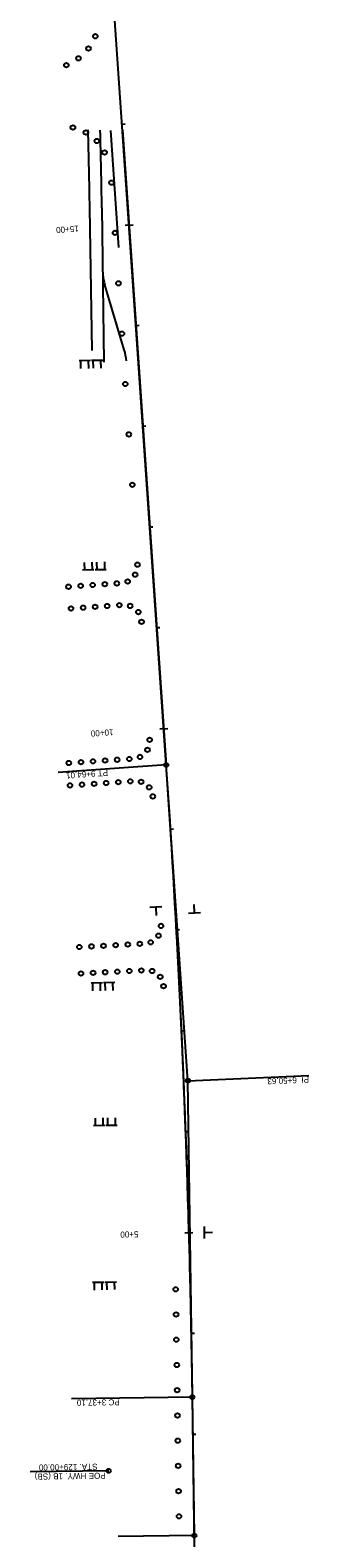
# Model space of a CAD drawing. Extents: x 1665984 to 1683035, y 227404 to 233856.
# Drawn here: x 1677283 to 1677559, y 230111 to 231605 of the extents above; entities that cross this region are included whole.
import ezdxf

# ---------------------------------------------------------------- set-up
doc = ezdxf.new("R2010")
doc.units = 0
for name, color, linetype in [('Default', 7, 'Continuous'), ('Level 47', 7, 'Continuous'), ('R_Horz Alg', 7, 'Continuous'), ('R_Horz Alg Annot', 7, 'Continuous'), ('R_MOT', 7, 'Continuous'), ('R_Striping', 7, 'Continuous'), ('S_EDGE_PAVEMENT', 7, 'Continuous')]:
    doc.layers.add(name, color=color, linetype=linetype)

msp = doc.modelspace()

# ---------------------------------------------------------------- linework, layer by layer
at = {"layer": 'Default'}
for p, q in [((1677413.3, 230736.3), (1677401.4, 230735.7)), ((1677407.4, 230735.8), (1677407.8, 230727.8)), ((1677445.7, 230730.6), (1677445.3, 230738.7)), ((1677439.8, 230730.1), (1677451.7, 230730.8)), ((1677455.1, 230419.7), (1677455.3, 230407.9)), ((1677455.4, 230413.8), (1677463.5, 230414))]:
    msp.add_line(p, q, dxfattribs=at)
at = {"layer": 'Level 47'}
for centre in [(1677347.3, 231598.8), (1677340.5, 231586.7), (1677318.6, 231570.2), (1677330.7, 231576.9), (1677325.1, 231508.4), (1677338, 231503.5), (1677348.8, 231495), (1677356.5, 231483.7), (1677363.4, 231453.8), (1677366.8, 231404), (1677370.2, 231354.1), (1677373.7, 231304.2), (1677377.1, 231254.3), (1677380.6, 231204.4), (1677384, 231154.5), (1677389.2, 231075.3), (1677379.4, 231058.7), (1677386.8, 231065.5), (1677320.8, 231053.5), (1677332.8, 231054.4), (1677344.7, 231055.2), (1677356.7, 231056), (1677368.7, 231056.8), (1677323.2, 231032), (1677335.2, 231032.8), (1677347.1, 231033.6), (1677359.1, 231034.4), (1677371.1, 231035.3), (1677381.9, 231034.5), (1677390, 231028.4), (1677393.2, 231018.7), (1677401.2, 230901.8), (1677333.1, 230879.7), (1677345, 230880.5), (1677357, 230881.3), (1677369, 230882.1), (1677381, 230882.9), (1677391.6, 230884.9), (1677399, 230891.9), (1677321.1, 230878.9), (1677322.2, 230856.7), (1677334.1, 230857.5), (1677346.1, 230858.3), (1677358.1, 230859.1), (1677370.1, 230859.9), (1677382, 230860.7), (1677392.7, 230860.3), (1677400.8, 230854.8), (1677404.3, 230845.8), (1677412.5, 230717.5), (1677402.2, 230701.3), (1677409.9, 230707.8), (1677331.5, 230696.6), (1677343.5, 230697.2), (1677355.5, 230697.8), (1677367.5, 230698.4), (1677379.5, 230699.1), (1677391.4, 230699.7), (1677333.1, 230670.4), (1677345.1, 230671), (1677357.1, 230671.6), (1677369.1, 230672.2), (1677381, 230672.8), (1677393, 230673.4), (1677403.6, 230672.8), (1677411.7, 230667.1), (1677415, 230657.8), (1677427, 230357.5), (1677427.4, 230332.6), (1677427.7, 230307.6), (1677428.1, 230282.6), (1677428.5, 230257.6), (1677428.8, 230232.6), (1677429.2, 230207.6), (1677429.5, 230182.6), (1677429.9, 230157.6), (1677430.3, 230132.6)]:
    msp.add_circle(centre, 2.25, dxfattribs=at)
at = {"layer": 'R_Horz Alg'}
for p, q in [((1677417.6, 230877), (1677316.6, 232344.1)), ((1677445.5, 230113.6), (1677443.6, 230250.7))]:
    msp.add_line(p, q, dxfattribs=at)
msp.add_arc((1665985.6, 230089.6), 11459.2, 0.80558, 3.94011, dxfattribs=at)
at = {"layer": 'R_Horz Alg Annot'}
for p, q in [((1677417.6, 230877), (1677310.4, 230869.6)), ((1677439.2, 230564.2), (1677417.6, 230877)), ((1677443.6, 230250.7), (1677439.2, 230564.2))]:
    msp.add_line(p, q, dxfattribs=at)
for points in [[(1677376.9, 231511.7), (1677373.9, 231511.5)], [(1677376.8, 231411.5), (1677384.8, 231412)], [(1677390.7, 231312.2), (1677387.7, 231312)], [(1677397.5, 231212.4), (1677394.6, 231212.2)], [(1677404.4, 231112.6), (1677401.4, 231112.4)], [(1677411.3, 231012.9), (1677408.3, 231012.7)], [(1677411.2, 230912.6), (1677419.2, 230913.2)], [(1677424.9, 230813.3), (1677421.9, 230813.1)], [(1677430.7, 230713.5), (1677427.7, 230713.3)], [(1677435.7, 230613.6), (1677432.7, 230613.4)], [(1677439.2, 230564.2), (1677559.1, 230569.2)], [(1677439.9, 230513.6), (1677436.9, 230513.5)], [(1677436.1, 230413.5), (1677444.1, 230413.7)], [(1677445.5, 230313.7), (1677442.5, 230313.6)], [(1677443.6, 230250.7), (1677323.6, 230249)], [(1677447.1, 230213.7), (1677444.1, 230213.6)], [(1677360.6, 230177.7), (1677282.7, 230176.6)], [(1677445.5, 230113.6), (1677370.1, 230112.6)]]:
    msp.add_lwpolyline(points, dxfattribs=at)
for centre in [(1677417.6, 230877), (1677439.2, 230564.2), (1677443.6, 230250.7), (1677360.6, 230177.7), (1677445.5, 230113.6)]:
    msp.add_circle(centre, 2, dxfattribs=at)
at = {"layer": 'R_MOT'}
for p, q in [((1677342.5, 231277.5), (1677331.3, 231277.3)), ((1677333.1, 231269.7), (1677333, 231277.4)), ((1677340.8, 231269.8), (1677340.6, 231277.5)), ((1677354.8, 231277.7), (1677343.6, 231277.5)), ((1677345.4, 231269.9), (1677345.3, 231277.6)), ((1677353.1, 231270), (1677352.9, 231277.7)), ((1677336.3, 231077.6), (1677336.5, 231070)), ((1677344, 231077.8), (1677344.1, 231070.1)), ((1677348.6, 231077.8), (1677348.7, 231070.2)), ((1677356.3, 231078), (1677356.4, 231070.3)), ((1677345.9, 231070.1), (1677334.7, 231069.9)), ((1677358.2, 231070.3), (1677347, 231070.1)), ((1677354.3, 230661.1), (1677343.1, 230660.9)), ((1677345, 230653.2), (1677344.8, 230660.9)), ((1677352.6, 230653.3), (1677352.5, 230661)), ((1677366.6, 230661.3), (1677355.4, 230661.1)), ((1677357.3, 230653.4), (1677357.1, 230661.1)), ((1677364.9, 230653.5), (1677364.8, 230661.2)), ((1677347.1, 230527.2), (1677347.2, 230519.5)), ((1677354.7, 230527.3), (1677354.8, 230519.6)), ((1677359.4, 230527.4), (1677359.5, 230519.7)), ((1677367, 230527.5), (1677367.1, 230519.9)), ((1677356.7, 230519.7), (1677345.4, 230519.5)), ((1677369, 230519.9), (1677357.7, 230519.7)), ((1677344.6, 230364.5), (1677355.9, 230364.7)), ((1677346.6, 230356.8), (1677346.5, 230364.5)), ((1677354.2, 230357), (1677354.1, 230364.6)), ((1677356.9, 230364.7), (1677368.2, 230364.9)), ((1677358.9, 230357), (1677358.8, 230364.7)), ((1677366.5, 230357.2), (1677366.4, 230364.8))]:
    msp.add_line(p, q, dxfattribs=at)
at = {"layer": 'R_Striping'}
for p, q in [((1677374.3, 231506.2), (1677417.6, 230877)), ((1677459.2, 229138.8), (1677443.6, 230250.7))]:
    msp.add_line(p, q, dxfattribs=at)
for start, end in [(1.7228, 3.94011), (0.80558, 1.49023)]:
    msp.add_arc((1665985.6, 230089.6), 11459.2, start, end, dxfattribs=at)
at = {"layer": 'S_EDGE_PAVEMENT'}
for p, q in [((1677362.3, 231505.4), (1677370.3, 231389.7)), ((1677341.7, 231428.6), (1677343.8, 231287.6)), ((1677353.7, 231428.8), (1677355.9, 231276)), ((1677376, 231288.1), (1677356.6, 231352.6))]:
    msp.add_line(p, q, dxfattribs=at)
for centre, radius, start, end in [((1671600.8, 231345.3), 5741.6, 0.83062, 1.6037), ((1671600.8, 231345.3), 5753.6, 0.83062, 1.59711), ((1677404.5, 231367), 50, 184.788, 196.7573), ((1677328.2, 231273.7), 50, 3.9401, 16.7573)]:
    msp.add_arc(centre, radius, start, end, dxfattribs=at)

# ---------------------------------------------------------------- texts
at = {"layer": 'R_Horz Alg Annot'}
for s, rotation, p in [('15+00', 183.9401, (1677330.7, 231411.3)), ('10+00', 183.9401, (1677365.1, 230912.5)), ('PT 9+64.01', 183.9401, (1677359.7, 230872.2)), ('PI  6+50.63', 182.3728, (1677559.1, 230568.2)), ('5+00', 181.6201, (1677390.1, 230415.2)), ('PC 3+37.10', 180.8056, (1677371.5, 230248.7)), ('STA. 129+00.00', 180.8056, (1677349.5, 230184.8)), ('POE HWY. 1B (SB)', 180.8056, (1677357.6, 230175.9))]:
    msp.add_text(s, height=6, rotation=rotation, dxfattribs=at).set_placement(p)

doc.saveas('drawing.dxf')
